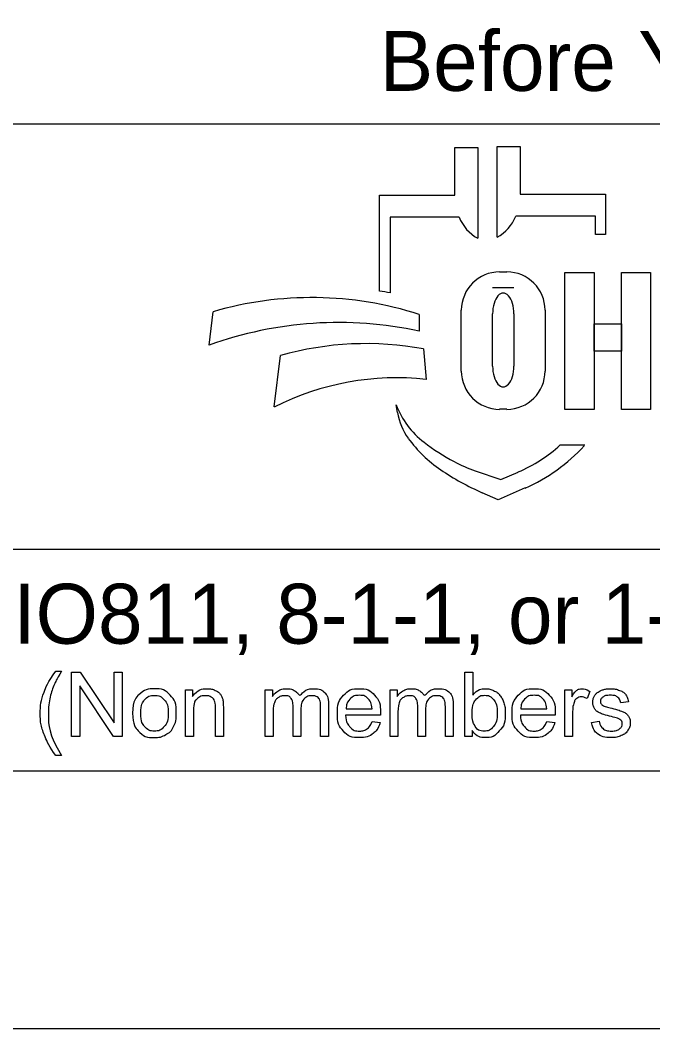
# Model space of a CAD drawing. Extents: x -19 to 40.8, y -1.8 to 26.1.
# Drawn here: x 15.218 to 16.695, y 0.5 to 2.856 of the extents above; entities that cross this region are included whole.
import ezdxf

# ---------------------------------------------------------------- set-up
doc = ezdxf.new("R2010")
doc.units = 0
for name, color, linetype in [('SH_Border', 7, 'Continuous'), ('SH_Data', 7, 'Continuous'), ('SH_Text', 7, 'Continuous')]:
    doc.layers.add(name, color=color, linetype=linetype)

msp = doc.modelspace()

# ---------------------------------------------------------------- linework, layer by layer
at = {"layer": 'SH_Border'}
msp.add_lwpolyline([(1.5, 21.5), (33.5, 21.5), (33.5, 0.5), (1.5, 0.5)], close=True, dxfattribs=at)
at = {"layer": 'SH_Data'}
for p, q in [((14.8767, 2.6144), (19.1267, 2.6144)), ((19.1267, 1.6197), (14.8767, 1.6197)), ((19.1267, 1.1019), (14.8767, 1.1019))]:
    msp.add_line(p, q, dxfattribs=at)
at = {"layer": 'SH_Text'}
for p, q in [((16.2327, 2.4474), (16.2327, 2.5589)), ((16.2327, 2.5589), (16.2864, 2.5589)), ((16.2864, 2.5589), (16.2864, 2.3468)), ((16.332, 2.3491), (16.332, 2.5612)), ((16.332, 2.5612), (16.3857, 2.5612)), ((16.3857, 2.5612), (16.3857, 2.4497)), ((16.0568, 2.2235), (16.0568, 2.4474)), ((16.0568, 2.4474), (16.2327, 2.4474)), ((16.3857, 2.4497), (16.5849, 2.4497)), ((16.5849, 2.4497), (16.5849, 2.3559)), ((16.082, 2.3959), (16.082, 2.2191)), ((16.2431, 2.3959), (16.082, 2.3959)), ((16.5616, 2.3983), (16.3753, 2.3983)), ((16.5616, 2.3559), (16.5616, 2.3983)), ((16.5849, 2.3559), (16.5616, 2.3559)), ((16.3377, 2.2682), (16.3543, 2.2682)), ((16.371, 2.2312), (16.3212, 2.2312)), ((15.6594, 2.0972), (15.6688, 2.1753)), ((16.1501, 2.1688), (16.1501, 2.13)), ((16.2482, 2.0367), (16.2482, 2.1787)), ((16.3212, 2.0481), (16.3212, 2.1705)), ((16.3709, 2.1705), (16.3709, 2.0481)), ((16.4437, 2.1787), (16.4437, 2.0367)), ((16.16, 2.0882), (16.1663, 2.0173)), ((15.8112, 1.9527), (15.8259, 2.0728)), ((16.0989, 1.9398), (16.0959, 1.9577)), ((16.3543, 1.9473), (16.3377, 1.9473)), ((16.4792, 1.8639), (16.5366, 1.8639)), ((16.2808, 1.8035), (16.3402, 1.783)), ((16.3402, 1.783), (16.3812, 1.8008)), ((16.3342, 1.736), (16.2968, 1.7525)), ((16.3975, 1.7635), (16.3342, 1.736))]:
    msp.add_line(p, q, dxfattribs=at)
for points in [[(16.4901, 2.2672), (16.5581, 2.2672), (16.5581, 1.9472), (16.4901, 1.9472)], [(16.6223, 2.2672), (16.6903, 2.2672), (16.6903, 1.9472), (16.6223, 1.9472)], [(16.5581, 2.1473), (16.6223, 2.1473), (16.6223, 2.0833), (16.5581, 2.0833)]]:
    msp.add_lwpolyline(points, close=True, dxfattribs=at)
for points in [[(15.3013, 1.3357), (15.3145, 1.3357)], [(15.338, 1.183), (15.338, 1.3332), (15.3584, 1.3332), (15.4374, 1.2152), (15.4374, 1.3332), (15.4564, 1.3332), (15.4564, 1.183), (15.4361, 1.183), (15.357, 1.3009), (15.357, 1.183), (15.338, 1.183)], [(16.2735, 1.183), (16.2565, 1.183), (16.2565, 1.3332), (16.2749, 1.3332), (16.2749, 1.2797)], [(15.604, 1.183), (15.604, 1.2919), (15.6206, 1.2919), (15.6206, 1.2764)], [(15.7904, 1.183), (15.7904, 1.2919), (15.8069, 1.2919), (15.8069, 1.2765)], [(16.0818, 1.183), (16.0818, 1.2919), (16.0983, 1.2919), (16.0983, 1.2765)], [(16.4896, 1.183), (16.4896, 1.2919), (16.5062, 1.2919), (16.5062, 1.2754)], [(16.5486, 1.2884), (16.5422, 1.2713)], [(15.6924, 1.2499), (15.6924, 1.183), (15.6739, 1.183), (15.6739, 1.2492)], [(15.8735, 1.2462), (15.8735, 1.183), (15.8551, 1.183), (15.8551, 1.2537)], [(15.9379, 1.2577), (15.9379, 1.183), (15.9195, 1.183), (15.9195, 1.2515)], [(16.1649, 1.2462), (16.1649, 1.183), (16.1465, 1.183), (16.1465, 1.2537)], [(16.2293, 1.2577), (16.2293, 1.183), (16.2109, 1.183), (16.2109, 1.2515)], [(16.6386, 1.2637), (16.6205, 1.2613)], [(15.6224, 1.2424), (15.6224, 1.183), (15.604, 1.183)], [(15.8089, 1.2394), (15.8089, 1.183), (15.7904, 1.183)], [(16.0592, 1.2327), (15.978, 1.2327)], [(15.979, 1.2478), (16.0398, 1.2478)], [(16.1002, 1.2394), (16.1002, 1.183), (16.0818, 1.183)], [(16.4672, 1.2327), (16.386, 1.2327)], [(16.387, 1.2478), (16.4478, 1.2478)], [(16.508, 1.24), (16.508, 1.183), (16.4896, 1.183)], [(16.0396, 1.2181), (16.0587, 1.2157)], [(16.4476, 1.2181), (16.4666, 1.2157)], [(16.5522, 1.2155), (16.5704, 1.2184)], [(16.2735, 1.1966), (16.2735, 1.183)], [(15.3145, 1.1388), (15.3013, 1.1388)]]:
    msp.add_lwpolyline(points, dxfattribs=at)
for centre, radius, start, end in [((16.3345, 2.4327), 0.0985, 201.9296, 240.7469), ((16.2839, 2.435), 0.0985, 299.2531, 338.0704), ((16.3377, 2.1787), 0.0895, 90, 180), ((16.3543, 2.1787), 0.0895, 0, 90), ((15.9286, 1.4145), 0.8191, 79.2074, 81.0007), ((15.8989, 1.3892), 0.8191, 72.1402, 106.3144), ((15.9619, 1.2581), 0.8919, 77.8238, 109.8274), ((16.0258, 1.3685), 0.7322, 79.44, 105.8467), ((16.3377, 2.0367), 0.0895, 180, 270), ((16.3543, 2.0367), 0.0895, 270, 0), ((16.0979, 1.3852), 0.6357, 83.8248, 116.8021), ((16.2832, 2.0298), 0.2008, 201.0457, 232.5314), ((16.2402, 1.9639), 0.1433, 189.6817, 216.0884), ((16.3739, 2.0613), 0.3088, 216.0884, 235.7167), ((16.4758, 2.281), 0.5173, 232.5314, 241.794), ((16.2378, 2.1313), 0.3602, 293.4582, 312.0712), ((16.2378, 2.1313), 0.401, 293.4582, 317.8286), ((16.3906, 2.1222), 0.3371, 241.794, 250.9821), ((16.5404, 2.3056), 0.6044, 235.7167, 246.2325)]:
    msp.add_arc(centre, radius, start, end, dxfattribs=at)
for centre, start_param, end_param in [((16.3461, 2.1705), 4.712389, 7.853982), ((16.3461, 2.0481), 1.570796, 4.712389)]:
    msp.add_ellipse(centre, major_axis=(0, 0.0484), ratio=0.514403, start_param=start_param, end_param=end_param, dxfattribs=at)
for points in [[(15.3013, 1.1388), (15.286, 1.1581), (15.2755, 1.1839), (15.2649, 1.2097), (15.2649, 1.2374), (15.2649, 1.2617), (15.2728, 1.2841), (15.282, 1.31), (15.3013, 1.3357)], [(15.3145, 1.3357), (15.3021, 1.3144), (15.2981, 1.3053), (15.2919, 1.2911), (15.2883, 1.2758), (15.2839, 1.2566), (15.2839, 1.2373), (15.2839, 1.188), (15.3145, 1.1388)], [(15.4805, 1.2374), (15.4805, 1.2676), (15.4973, 1.2822), (15.5113, 1.2943), (15.5315, 1.2943), (15.5539, 1.2943), (15.5682, 1.2796), (15.5824, 1.2649), (15.5824, 1.239), (15.5824, 1.218), (15.5761, 1.206), (15.5698, 1.1939), (15.5578, 1.1873), (15.5457, 1.1806), (15.5315, 1.1806), (15.5087, 1.1806), (15.4946, 1.1953), (15.4805, 1.2099), (15.4805, 1.2374)], [(15.4995, 1.2374), (15.4995, 1.2165), (15.5086, 1.2061), (15.5177, 1.1957), (15.5315, 1.1957), (15.5452, 1.1957), (15.5543, 1.2062), (15.5634, 1.2166), (15.5634, 1.238), (15.5634, 1.2582), (15.5542, 1.2686), (15.5451, 1.279), (15.5315, 1.279), (15.5177, 1.279), (15.5086, 1.2687), (15.4995, 1.2583), (15.4995, 1.2374)], [(15.6206, 1.2764), (15.6326, 1.2943), (15.6552, 1.2943), (15.665, 1.2943), (15.6733, 1.2907), (15.6815, 1.2872), (15.6856, 1.2815), (15.6897, 1.2757), (15.6913, 1.2678), (15.6924, 1.2627), (15.6924, 1.2499)], [(15.6739, 1.2492), (15.6739, 1.2604), (15.6718, 1.266), (15.6696, 1.2716), (15.6642, 1.2749), (15.6587, 1.2782), (15.6513, 1.2782), (15.6395, 1.2782), (15.631, 1.2708), (15.6224, 1.2633), (15.6224, 1.2424)], [(15.8069, 1.2765), (15.812, 1.2845), (15.8205, 1.2894), (15.829, 1.2943), (15.8399, 1.2943), (15.852, 1.2943), (15.8597, 1.2892), (15.8675, 1.2842), (15.8706, 1.2752), (15.8836, 1.2943), (15.9043, 1.2943), (15.9205, 1.2943), (15.9292, 1.2853), (15.9379, 1.2763), (15.9379, 1.2577)], [(15.8551, 1.2537), (15.8551, 1.2659), (15.8506, 1.2721), (15.8461, 1.2782), (15.8358, 1.2782), (15.828, 1.2782), (15.8214, 1.2741), (15.8148, 1.27), (15.8118, 1.2622), (15.8089, 1.2543), (15.8089, 1.2394)], [(15.9195, 1.2515), (15.9195, 1.2626), (15.9177, 1.2674), (15.9159, 1.2723), (15.9112, 1.2753), (15.9065, 1.2782), (15.9002, 1.2782), (15.8887, 1.2782), (15.8811, 1.2706), (15.8735, 1.263), (15.8735, 1.2462)], [(16.0587, 1.2157), (16.0542, 1.1991), (16.042, 1.1898), (16.0298, 1.1806), (16.0108, 1.1806), (15.987, 1.1806), (15.973, 1.1953), (15.959, 1.21), (15.959, 1.2365), (15.959, 1.264), (15.9732, 1.2791), (15.9873, 1.2943), (16.0098, 1.2943), (16.0316, 1.2943), (16.0454, 1.2794), (16.0593, 1.2645), (16.0593, 1.2376), (16.0593, 1.236), (16.0592, 1.2327)], [(16.0398, 1.2478), (16.0386, 1.2616), (16.0328, 1.2685), (16.024, 1.2791), (16.01, 1.2791), (15.9973, 1.2791), (15.9886, 1.2706), (15.98, 1.2621), (15.979, 1.2478)], [(16.0983, 1.2765), (16.1034, 1.2845), (16.1119, 1.2894), (16.1204, 1.2943), (16.1313, 1.2943), (16.1434, 1.2943), (16.1511, 1.2892), (16.1588, 1.2842), (16.162, 1.2752), (16.1749, 1.2943), (16.1957, 1.2943), (16.2119, 1.2943), (16.2206, 1.2853), (16.2293, 1.2763), (16.2293, 1.2577)], [(16.1465, 1.2537), (16.1465, 1.2659), (16.1419, 1.2721), (16.1374, 1.2782), (16.1272, 1.2782), (16.1194, 1.2782), (16.1128, 1.2741), (16.1062, 1.27), (16.1032, 1.2622), (16.1002, 1.2543), (16.1002, 1.2394)], [(16.2109, 1.2515), (16.2109, 1.2626), (16.2091, 1.2674), (16.2073, 1.2723), (16.2026, 1.2753), (16.1979, 1.2782), (16.1915, 1.2782), (16.18, 1.2782), (16.1725, 1.2706), (16.1649, 1.263), (16.1649, 1.2462)], [(16.2733, 1.2383), (16.2733, 1.2187), (16.2786, 1.21), (16.2873, 1.1957), (16.3021, 1.1957), (16.3142, 1.1957), (16.323, 1.2062), (16.3318, 1.2167), (16.3318, 1.2375), (16.3318, 1.2589), (16.3233, 1.269), (16.3149, 1.2791), (16.3029, 1.2791), (16.2909, 1.2791), (16.2821, 1.2686), (16.2733, 1.2581), (16.2733, 1.2383)], [(16.2749, 1.2797), (16.2866, 1.2943), (16.3047, 1.2943), (16.3147, 1.2943), (16.3237, 1.2902), (16.3326, 1.2862), (16.3384, 1.2788), (16.3442, 1.2715), (16.3475, 1.2612), (16.3508, 1.2508), (16.3508, 1.2391), (16.3508, 1.2111), (16.3369, 1.1959), (16.3231, 1.1806), (16.3037, 1.1806), (16.2845, 1.1806), (16.2735, 1.1966)], [(16.4666, 1.2157), (16.4621, 1.1991), (16.45, 1.1898), (16.4378, 1.1806), (16.4188, 1.1806), (16.395, 1.1806), (16.381, 1.1953), (16.367, 1.21), (16.367, 1.2365), (16.367, 1.264), (16.3811, 1.2791), (16.3953, 1.2943), (16.4178, 1.2943), (16.4396, 1.2943), (16.4534, 1.2794), (16.4673, 1.2645), (16.4673, 1.2376), (16.4673, 1.236), (16.4672, 1.2327)], [(16.4478, 1.2478), (16.4466, 1.2616), (16.4408, 1.2685), (16.432, 1.2791), (16.418, 1.2791), (16.4053, 1.2791), (16.3966, 1.2706), (16.388, 1.2621), (16.387, 1.2478)], [(16.5062, 1.2754), (16.5125, 1.2869), (16.5179, 1.2906), (16.5233, 1.2943), (16.5297, 1.2943), (16.539, 1.2943), (16.5486, 1.2884)], [(16.5422, 1.2713), (16.5354, 1.2753), (16.5287, 1.2753), (16.5227, 1.2753), (16.5179, 1.2716), (16.5131, 1.268), (16.5111, 1.2615), (16.508, 1.2517), (16.508, 1.24)], [(16.6205, 1.2613), (16.6193, 1.2697), (16.6134, 1.2744), (16.6075, 1.2791), (16.5967, 1.2791), (16.584, 1.2791), (16.5786, 1.2749), (16.5731, 1.2707), (16.5731, 1.2651), (16.5731, 1.2615), (16.5754, 1.2586), (16.5776, 1.2557), (16.5825, 1.2537), (16.5852, 1.2527), (16.5988, 1.249), (16.6184, 1.2438), (16.6261, 1.2404), (16.6339, 1.2371), (16.6383, 1.2308), (16.6427, 1.2244), (16.6427, 1.215), (16.6427, 1.2058), (16.6373, 1.1977), (16.6319, 1.1895), (16.6218, 1.1851), (16.6116, 1.1806), (16.5988, 1.1806), (16.5775, 1.1806), (16.5664, 1.1894), (16.5553, 1.1982), (16.5522, 1.2155)], [(16.5704, 1.2184), (16.5719, 1.2074), (16.579, 1.2016), (16.586, 1.1957), (16.5986, 1.1957), (16.6114, 1.1957), (16.6175, 1.2009), (16.6237, 1.2061), (16.6237, 1.2131), (16.6237, 1.2193), (16.6183, 1.2229), (16.6145, 1.2254), (16.5994, 1.2292), (16.5791, 1.2343), (16.5712, 1.238), (16.5634, 1.2418), (16.5593, 1.2484), (16.5553, 1.255), (16.5553, 1.2629), (16.5553, 1.2702), (16.5586, 1.2764), (16.5619, 1.2826), (16.5677, 1.2867), (16.572, 1.2899), (16.5794, 1.2921), (16.5869, 1.2943), (16.5954, 1.2943), (16.6082, 1.2943), (16.6179, 1.2906), (16.6276, 1.2869), (16.6322, 1.2806), (16.6368, 1.2743), (16.6386, 1.2637)], [(15.978, 1.2327), (15.979, 1.2148), (15.9882, 1.2052), (15.9973, 1.1957), (16.0109, 1.1957), (16.0211, 1.1957), (16.0282, 1.2011), (16.0354, 1.2064), (16.0396, 1.2181)], [(16.386, 1.2327), (16.387, 1.2148), (16.3962, 1.2052), (16.4053, 1.1957), (16.4189, 1.1957), (16.4291, 1.1957), (16.4362, 1.2011), (16.4434, 1.2064), (16.4476, 1.2181)]]:
    msp.add_open_spline(points, degree=3, dxfattribs=at)

# ---------------------------------------------------------------- texts
for s, p in [('Before You Dig', (16.0575, 2.6912)), ('OHIO811, 8-1-1, or 1-800-362-2764', (14.9212, 1.3997))]:
    msp.add_text(s, height=0.14, dxfattribs=at).set_placement(p)

doc.saveas('drawing.dxf')
